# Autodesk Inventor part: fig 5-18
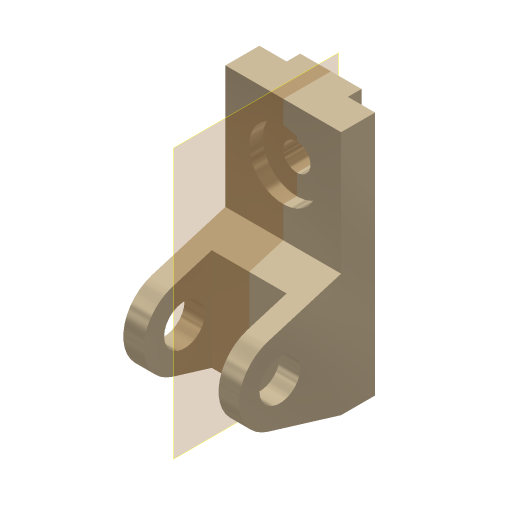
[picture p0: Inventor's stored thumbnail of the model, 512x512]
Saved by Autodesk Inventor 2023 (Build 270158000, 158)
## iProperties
Created: 2001-11
Part Number: fig 5-18
Document SubType Name: Modeling
Designer: Renu Muthoo
Density: 1 g/cm^3
Material: Generic
Appearance: Metal-Titanium (Polished)
Control State: 0
Master: False
Checked Out: False
Shininess: 65.0
Angle Display Precision: 2
Document Length Units: 11269
Document Angle Units: 11279
Document Time Units: 11290
Document Mass Units: 11283
Document Length Units Precision: 3
Document Angle Units Precision: 2
Compacted: False
Density: 0.0
Volumn: 0.0
Area: 0.0
PropertySet Name: Model Information
Author: Renu Muthoo
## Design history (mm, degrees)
node "Sketch1"
sketch "Sketch2"
  geometry: L1 (33.257, 104.664)-(33.257, -75.336); L2 (33.257, -75.336)-(8.257, -75.336); L3 (8.257, -75.336)-(-45.451, -59.045); L4 (-45.451, -1.628)-(8.257, 14.664); L5 (8.257, 14.664)-(8.257, 104.664); L6 (8.257, 104.664)-(33.257, 104.664); C1 r 15 at (-36.743, -30.336); A1 r 30 centre (-36.743, -30.336) between (-45.451, -1.628) and (-45.451, -59.045)
  constraints: 12 end point, 2 centre point, 2 equal length, 2 parallel, 2 point on circle, 2 tangent, 1 coincident, 1 perpendicular, 1 vertical
  dimensions: "d0" = 180 distance of L1.start L1.end; "d1" = 30 radius of A1; "d2" = 25 distance of L5.end L1.start; "d3" = 45 distance from line of L2 A1.centre; "d4" = 70 distance from line of L1 A1.centre; "d5" = 30 diameter of C1
extrude "Extrusion1" new body sketch "Sketch2" distance "d6" = 85; taper "d7" = 0 deg
workplane "Work Plane1"
sketch "Sketch3"
  geometry: L1 (15, 62.364)-(70, 62.364); L2 (70, 62.364)-(70, -52.386); L3 (70, -52.386)-(15, -52.386); L4 (15, -52.386)-(15, 62.364); L5 (0, -45)-(0, -28.708) reference
  constraints: 8 end point, 2 parallel, 1 horizontal, 1 perpendicular
  dimensions: "d8" = 55 distance of L1.start L1.end; "d9" = 15 distance between parallel lines of L5 L4
extrude "Extrusion2" cut sketch "Sketch3" distance "d10" = 50; taper "d11" = 0 deg
sketch "Sketch4"
  geometry: L1 (0, 25)-(85, 25) reference; L2 (0, 0)-(0, 25) reference; L3 (20, 25)-(65, 25); L4 (65, 25)-(65, 35); L5 (65, 35)-(20, 35); L6 (20, 35)-(20, 25)
  constraints: 8 end point, 2 parallel, 1 horizontal, 1 perpendicular, 1 point on line
  dimensions: "d12" = 45 distance of L4.end L5.end; "d13" = 10 distance of L3.end L4.end; "d14" = 20 distance between parallel lines of L2 L6
extrude "Extrusion3" join sketch "Sketch4" stored distance "d15" = 50; taper "d16" = 0 deg
sketch "Sketch5"
  geometry: L1 (85, 0)-(85, 90) reference; L2 (0, 90)-(85, 90) reference; 1 further point
  dimensions: "d17" = 42 distance from line of L2 point (42.5, 48); "d18" = 42.5 distance from line of L1 point (42.5, 48)
hole "Hole1" sketch "Sketch5" at (42.5, 48) diameter "d19" = 20; stored, may be unused: countersink angle "d23" = 82 deg, drill point angle "d25" = 118 deg; dims "d20" = 6, "d21" = 50, "d22" = 10, "d24" = 8
workplane "Work Plane9"
body "Solid1"
